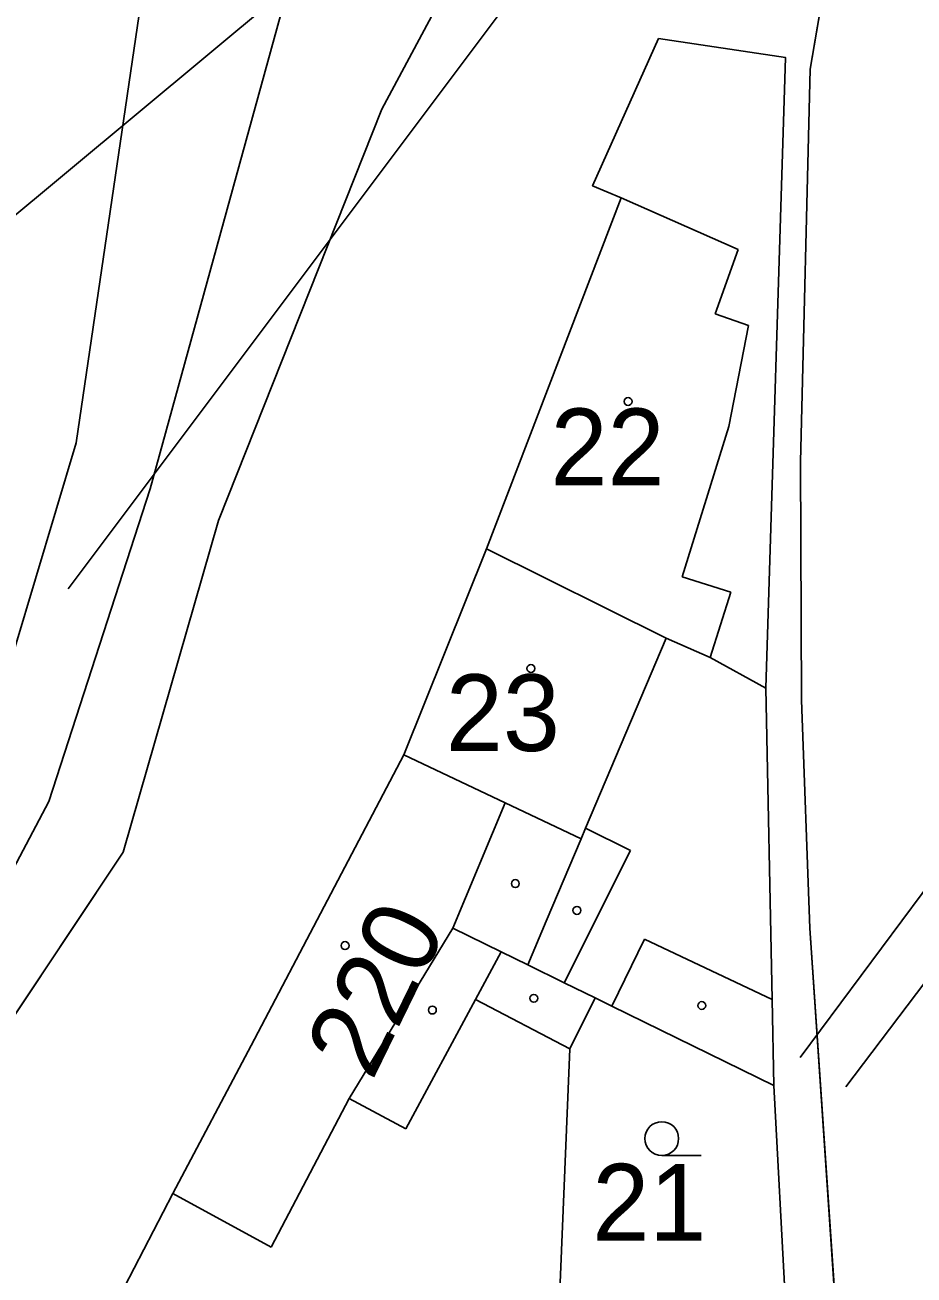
# Model space of a CAD drawing. Extents: x -537341 to -532984, y -1143469 to -1141314.
# Drawn here: x -534096.7 to -534057.3, y -1143141.1 to -1143085.7 of the extents above; entities that cross this region are included whole.
import ezdxf

# ---------------------------------------------------------------- set-up
doc = ezdxf.new("R2010")
doc.units = 0
for name, color, linetype in [('Hranice parcel', 7, 'Continuous'), ('parcelní_č_2000', 7, 'Continuous'), ('u_obec_Horní_Moš', 7, 'Continuous'), ('u_osa_toku', 7, 'Continuous'), ('u_pricne', 7, 'Continuous'), ('u_ŘSD', 7, 'Continuous'), ('Vnitřní kresba', 7, 'Continuous'), ('Značky budov', 7, 'Continuous'), ('Značky kultur', 7, 'Continuous')]:
    doc.layers.add(name, color=color, linetype=linetype)

msp = doc.modelspace()

# ---------------------------------------------------------------- linework, layer by layer
at = {"layer": 'Hranice parcel'}
for p, q in [((-534057.96, -1143064.19), (-534061.91, -1143087.65)), ((-534079.93, -1143118.06), (-534076.27, -1143108.93)), ((-534063.52, -1143132.72), (-534062.89, -1143144.66))]:
    msp.add_line(p, q, dxfattribs=at)
for points in [[(-534057.96, -1143064.19), (-534059.64, -1143064.14), (-534074.56, -1143079.61), (-534078.59, -1143085.09), (-534080.91, -1143089.42), (-534088.16, -1143107.66), (-534092.38, -1143122.37), (-534099.66, -1143133.29), (-534105.29, -1143138.59), (-534106.3, -1143138.42), (-534110.81, -1143141.06), (-534111.69, -1143142.47), (-534119.94, -1143145.27), (-534133.44, -1143145.32), (-534146.47, -1143141.81), (-534184.24, -1143128.27), (-534195.29, -1143122.4), (-534195.41, -1143122.63), (-534196.29, -1143122.15), (-534196.18, -1143121.93), (-534253.1, -1143091.68), (-534282.11, -1143079.68)], [(-534090.7, -1143078.55), (-534094.46, -1143104.22), (-534099.89, -1143122.31), (-534105.1, -1143130.32), (-534109.71, -1143134.37), (-534110.15, -1143136.73), (-534114.49, -1143139.24), (-534116.81, -1143138.09), (-534121.68, -1143139.5)], [(-534076.27, -1143108.93), (-534070.29, -1143093.36), (-534071.56, -1143092.82), (-534068.63, -1143086.29), (-534063.01, -1143087.13), (-534063.88, -1143115.1)], [(-534061.91, -1143087.65), (-534062.34, -1143105.07), (-534062.29, -1143115.63), (-534061.93, -1143125.74), (-534060.79, -1143142.46), (-534058.08, -1143166.45), (-534054.98, -1143192.46), (-534048.78, -1143241.39), (-534046.39, -1143261.54)], [(-534076.27, -1143108.93), (-534068.3, -1143112.88), (-534066.34, -1143113.75), (-534063.88, -1143115.1)], [(-534063.88, -1143115.1), (-534063.6, -1143128.91), (-534063.52, -1143132.72)], [(-534092.32, -1143141.66), (-534090.18, -1143137.52), (-534086.71, -1143130.95), (-534079.93, -1143118.06)], [(-534079.93, -1143118.06), (-534075.44, -1143120.19), (-534077.76, -1143125.75), (-534075.62, -1143126.8), (-534074.44, -1143127.38), (-534072.82, -1143128.17), (-534071.45, -1143128.84)], [(-534073.09, -1143143.62), (-534072.57, -1143131.1), (-534071.45, -1143128.84)], [(-534071.45, -1143128.84), (-534070.71, -1143129.2), (-534063.52, -1143132.72)]]:
    msp.add_lwpolyline(points, dxfattribs=at)
at = {"layer": 'u_obec_Horní_Moš'}
for p, q in [((-534061.91, -1143087.65), (-534057.96, -1143064.19)), ((-534079.93, -1143118.06), (-534076.27, -1143108.93)), ((-534099.66, -1143133.29), (-534092.38, -1143122.37)), ((-534063.52, -1143132.72), (-534062.89, -1143144.66))]:
    msp.add_line(p, q, dxfattribs=at)
for points in [[(-534090.7, -1143078.55), (-534094.46, -1143104.22), (-534099.89, -1143122.31), (-534105.1, -1143130.32), (-534109.71, -1143134.37), (-534110.15, -1143136.73)], [(-534078.59, -1143085.09), (-534080.91, -1143089.42), (-534088.16, -1143107.66), (-534092.38, -1143122.37)], [(-534092.38, -1143122.37), (-534088.16, -1143107.66), (-534080.91, -1143089.42), (-534078.59, -1143085.09)], [(-534076.27, -1143108.93), (-534070.29, -1143093.36), (-534071.56, -1143092.82), (-534068.63, -1143086.29), (-534063.01, -1143087.13), (-534063.88, -1143115.1)], [(-534062.29, -1143115.63), (-534062.34, -1143105.07), (-534061.91, -1143087.65)], [(-534063.88, -1143115.1), (-534063.6, -1143128.91), (-534063.52, -1143132.72)], [(-534060.79, -1143142.46), (-534061.93, -1143125.74), (-534062.29, -1143115.63)], [(-534092.32, -1143141.66), (-534090.18, -1143137.52), (-534086.71, -1143130.95), (-534079.93, -1143118.06)], [(-534092.38, -1143122.37), (-534099.66, -1143133.29), (-534105.29, -1143138.59), (-534106.3, -1143138.42), (-534110.81, -1143141.06), (-534111.69, -1143142.47), (-534119.94, -1143145.27), (-534133.44, -1143145.32), (-534146.47, -1143141.81), (-534184.24, -1143128.27)]]:
    msp.add_lwpolyline(points, dxfattribs=at)
at = {"layer": 'u_osa_toku'}
msp.add_lwpolyline([(-534255.2, -1143086.242), (-534194.495, -1143118.949), (-534158.208, -1143134.477), (-534141.073, -1143140.275), (-534130.725, -1143142.98), (-534122.661, -1143143.626), (-534114.813, -1143141.462), (-534105.041, -1143135.691), (-534099.556, -1143127.453), (-534095.683, -1143120.128), (-534091.183, -1143106.259), (-534085.121, -1143084.236), (-534081.698, -1143076.975), (-534079.417, -1143074.051), (-534076.981, -1143071.521), (-534075.983, -1143070.507), (-534074.271, -1143069.057), (-534072.483, -1143067.88), (-534069.692, -1143067.171), (-534065.2, -1143067.444), (-534033.387, -1143091.298), (-534029.938, -1143092.998)], dxfattribs=at)
at = {"layer": 'u_pricne'}
for p, q in [((-534094.823, -1143110.698), (-534021.005, -1143012.252)), ((-534008.415, -1143020.259), (-534107.407, -1143102.639)), ((-533988.923, -1143032.655), (-534062.355, -1143131.49)), ((-533986.083, -1143034.462), (-534060.326, -1143132.79))]:
    msp.add_line(p, q, dxfattribs=at)
at = {"layer": 'u_ŘSD'}
for p, q in [((-534057.96, -1143064.19), (-534061.91, -1143087.65)), ((-534062.29, -1143115.63), (-534061.93, -1143125.74)), ((-534061.93, -1143125.74), (-534060.79, -1143142.46))]:
    msp.add_line(p, q, dxfattribs=at)
msp.add_lwpolyline([(-534061.91, -1143087.65), (-534062.34, -1143105.07), (-534062.29, -1143115.63)], dxfattribs=at)
at = {"layer": 'Vnitřní kresba'}
for p, q in [((-534070.29, -1143093.36), (-534065.11, -1143095.65)), ((-534065.11, -1143095.65), (-534066.12, -1143098.5)), ((-534066.12, -1143098.5), (-534064.65, -1143099.02)), ((-534064.65, -1143099.02), (-534065.52, -1143103.49)), ((-534065.52, -1143103.49), (-534067.59, -1143110.17)), ((-534067.59, -1143110.17), (-534065.43, -1143110.84)), ((-534065.43, -1143110.84), (-534066.34, -1143113.75)), ((-534068.3, -1143112.88), (-534071.87, -1143121.31)), ((-534075.44, -1143120.19), (-534072.07, -1143121.79)), ((-534072.07, -1143121.79), (-534073.62, -1143125.44)), ((-534071.87, -1143121.31), (-534072.07, -1143121.79)), ((-534071.87, -1143121.31), (-534069.88, -1143122.3)), ((-534069.88, -1143122.3), (-534072.82, -1143128.17)), ((-534073.62, -1143125.44), (-534074.44, -1143127.38)), ((-534082.35, -1143133.3), (-534077.76, -1143125.75)), ((-534070.71, -1143129.2), (-534069.26, -1143126.24)), ((-534069.26, -1143126.24), (-534063.6, -1143128.91)), ((-534076.75, -1143128.91), (-534075.62, -1143126.8)), ((-534079.84, -1143134.65), (-534076.75, -1143128.91)), ((-534076.75, -1143128.91), (-534072.57, -1143131.1)), ((-534085.82, -1143139.9), (-534082.35, -1143133.3)), ((-534082.35, -1143133.3), (-534079.84, -1143134.65)), ((-534090.18, -1143137.52), (-534085.82, -1143139.9))]:
    msp.add_line(p, q, dxfattribs=at)
at = {"layer": 'Značky budov'}
for centre in [(-534069.987, -1143102.389), (-534074.297, -1143114.229), (-534074.987, -1143123.769), (-534072.257, -1143124.959), (-534082.537, -1143126.519), (-534074.167, -1143128.859), (-534078.667, -1143129.379), (-534066.717, -1143129.179)]:
    msp.add_circle(centre, 0.175, dxfattribs=at)
at = {"layer": 'Značky kultur'}
msp.add_line((-534068.493, -1143135.83), (-534066.743, -1143135.83), dxfattribs=at)
msp.add_circle((-534068.493, -1143135.08), 0.75, dxfattribs=at)

# ---------------------------------------------------------------- texts
at = {"layer": 'parcelní_č_2000'}
for s, p in [('22', (-534073.424, -1143106.1)), ('23', (-534078.068, -1143117.89)), ('21', (-534071.572, -1143139.6))]:
    msp.add_text(s, height=3.4, dxfattribs=at).set_placement(p)
msp.add_text('220', height=3.4, rotation=64, dxfattribs=at).set_placement((-534081.344, -1143132.57))

doc.saveas('drawing.dxf')
